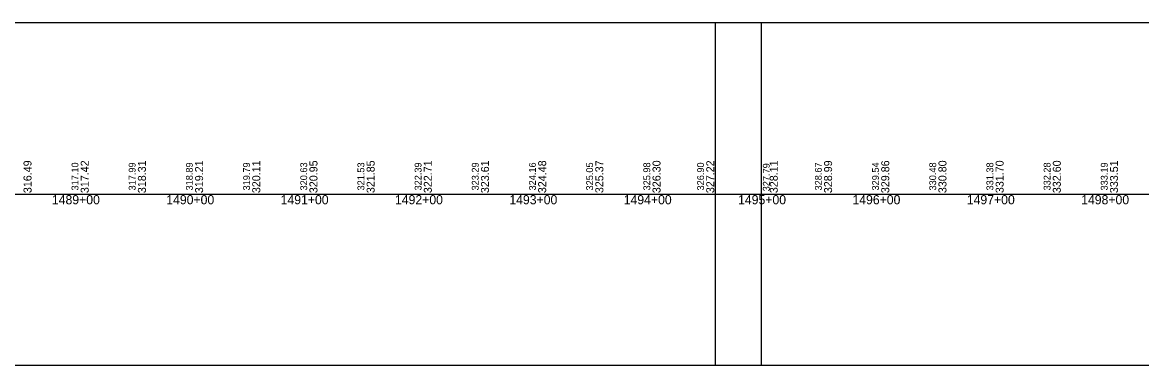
# Model space of a CAD drawing. Extents: x -3627 to 47473, y 2850 to 4350.
# Drawn here: x 36327 to 37306, y 2850 to 3150 of the extents above; entities that cross this region are included whole.
import ezdxf

# ---------------------------------------------------------------- set-up
doc = ezdxf.new("R2010")
doc.units = 0
for name, color, linetype in [('RD_DDB_StaTX', 7, 'Continuous'), ('RD_DDB_StripGrade', 7, 'Continuous'), ('RD_GPK_Profile_Cell', 7, 'Continuous'), ('RD_SHT_ShtClip', 7, 'Continuous')]:
    doc.layers.add(name, color=color, linetype=linetype)

msp = doc.modelspace()

# ---------------------------------------------------------------- linework, layer by layer
at = {"layer": 'RD_GPK_Profile_Cell'}
msp.add_line((1000, 3000), (46705.077602, 3000), dxfattribs=at)
at = {"layer": 'RD_SHT_ShtClip'}
for points in [[(35433.33, 3150), (36973.33, 3150), (36973.33, 2850), (35433.33, 2850)], [(36933.33, 3150), (38473.33, 3150), (38473.33, 2850), (36933.33, 2850)]]:
    msp.add_lwpolyline(points, close=True, dxfattribs=at)

# ---------------------------------------------------------------- texts
at = {"layer": 'RD_DDB_StaTX'}
for s, p in [('1489+00', (36353.125471, 2991)), ('1490+00', (36453.125471, 2991)), ('1491+00', (36553.125471, 2991)), ('1492+00', (36653.125471, 2991)), ('1493+00', (36753.125471, 2991)), ('1494+00', (36853.125471, 2991)), ('1495+00', (36953.125471, 2991)), ('1496+00', (37053.125471, 2991)), ('1497+00', (37153.125471, 2991)), ('1498+00', (37253.125471, 2991))]:
    msp.add_text(s, height=8, dxfattribs=at).set_placement(p)
at = {"layer": 'RD_DDB_StripGrade'}
for s, height, p in [('316.49', 7, (36335.33, 3000.75)), ('317.10', 6, (36376.33, 3003.073688)), ('317.42', 7, (36385.33, 3000.75)), ('317.99', 6, (36426.33, 3003.073688)), ('318.31', 7, (36435.33, 3000.75)), ('318.89', 6, (36476.33, 3003.073688)), ('319.21', 7, (36485.33, 3000.75)), ('319.79', 6, (36526.33, 3003.073688)), ('320.11', 7, (36535.33, 3000.75)), ('320.63', 6, (36576.33, 3003.073688)), ('320.95', 7, (36585.33, 3000.75)), ('321.53', 6, (36626.33, 3003.073688)), ('321.85', 7, (36635.33, 3000.75)), ('322.39', 6, (36676.33, 3003.073688)), ('322.71', 7, (36685.33, 3000.75)), ('323.29', 6, (36726.33, 3003.073688)), ('323.61', 7, (36735.33, 3000.75)), ('324.16', 6, (36776.33, 3003.073688)), ('324.48', 7, (36785.33, 3000.75)), ('325.05', 6, (36826.33, 3003.073688)), ('325.37', 7, (36835.33, 3000.75)), ('325.98', 6, (36876.33, 3003.073688)), ('326.30', 7, (36885.33, 3000.75)), ('326.90', 6, (36923.33, 3003.073688)), ('327.22', 7, (36932.313182, 3000.75)), ('327.79', 6, (36980.815828, 3002.33667)), ('328.11', 7, (36987.815828, 3000.75)), ('328.67', 6, (37026.33, 3003.073688)), ('328.99', 7, (37035.33, 3000.75)), ('329.54', 6, (37076.33, 3003.073688)), ('329.86', 7, (37085.33, 3000.75)), ('330.48', 6, (37126.33, 3003.073688)), ('330.80', 7, (37135.33, 3000.75)), ('331.38', 6, (37176.33, 3003.073688)), ('331.70', 7, (37185.33, 3000.75)), ('332.28', 6, (37226.33, 3003.073688)), ('332.60', 7, (37235.33, 3000.75)), ('333.19', 6, (37276.33, 3003.073688)), ('333.51', 7, (37285.33, 3000.75))]:
    msp.add_text(s, height=height, rotation=90, dxfattribs=at).set_placement(p)

doc.saveas('drawing.dxf')
